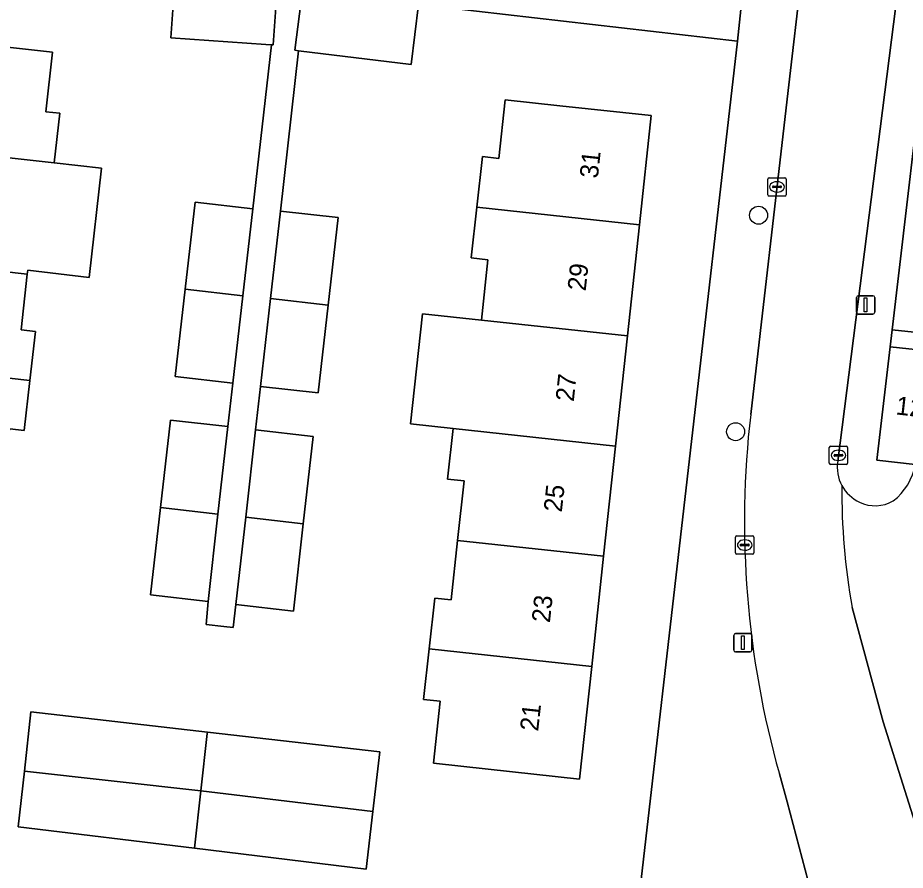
# Model space of a CAD drawing. Extents: x 162026 to 163502, y 387295 to 388169.
# Drawn here: x 162444.62 to 162492.97, y 387700.63 to 387747.09 of the extents above; entities that cross this region are included whole.
import ezdxf

# ---------------------------------------------------------------- set-up
doc = ezdxf.new("R2010")
doc.units = 0
for name, color, linetype in [('IMGEO_Boom', 7, 'Continuous'), ('IMGEO_Erf', 7, 'Continuous'), ('IMGEO_Groenvoorziening', 7, 'Continuous'), ('IMGEO_Kolk', 7, 'Continuous'), ('IMGEO_Lichtmast', 7, 'Continuous'), ('IMGEO_Pand', 7, 'Continuous'), ('IMGEO_Pand_nummerreeks', 7, 'Continuous'), ('IMGEO_Parkeervlak_open', 7, 'Continuous'), ('IMGEO_Rijbaan_lokaal_open', 7, 'Continuous'), ('IMGEO_Voetpad_open', 7, 'Continuous')]:
    doc.layers.add(name, color=color, linetype=linetype)

msp = doc.modelspace()

# ---------------------------------------------------------------- linework, layer by layer
at = {"layer": 'IMGEO_Boom'}
for centre in [(162484.977, 387736.328), (162483.728, 387724.532)]:
    msp.add_circle(centre, 0.489, dxfattribs=at)
at = {"layer": 'IMGEO_Erf'}
for points in [[(162495.6, 387752.476), (162494.973, 387750), (162494.279, 387747.259), (162492.259, 387730.082), (162494.645, 387729.836), (162520.514, 387727.17), (162539.426, 387725.085), (162541.672, 387745.5)], [(162478.34, 387698.075), (162483.821, 387745.82), (162466.456, 387747.814), (162466.055, 387744.538), (162459.921, 387745.291), (162458.93, 387736.554), (162462.069, 387736.197), (162461.528, 387731.428), (162460.986, 387726.646), (162457.846, 387727.002), (162457.577, 387724.631), (162460.716, 387724.275), (162460.176, 387719.515), (162459.636, 387714.756), (162456.497, 387715.112), (162456.355, 387713.866), (162455.849, 387713.923), (162454.88, 387714.033), (162454.985, 387715.28), (162451.845, 387715.638), (162452.388, 387720.397), (162452.932, 387725.167), (162456.072, 387724.809), (162456.342, 387727.183), (162453.203, 387727.541), (162453.744, 387732.292), (162454.286, 387737.042), (162457.426, 387736.684), (162458.444, 387745.612), (162458.142, 387745.633), (162452.965, 387745.998), (162453.181, 387749.067)], [(162443.545, 387745.548), (162446.519, 387745.215), (162446.155, 387741.965), (162446.903, 387741.882), (162446.6, 387739.174), (162449.179, 387738.885), (162448.504, 387732.942), (162445.16, 387733.326), (162445.136, 387733.112), (162444.796, 387730.079), (162445.578, 387729.992), (162445.28, 387727.328), (162444.975, 387724.601), (162444.184, 387724.69)]]:
    msp.add_lwpolyline(points, dxfattribs=at)
for points in [[(162469.946, 387739.524), (162470.827, 387739.424), (162471.171, 387742.616), (162474.154, 387742.294), (162479.125, 387741.758), (162478.483, 387735.806), (162477.83, 387729.752), (162477.182, 387723.75), (162476.535, 387717.75), (162475.887, 387711.744), (162475.225, 387705.604), (162470.254, 387706.14), (162467.271, 387706.462), (162467.635, 387709.842), (162466.728, 387709.944), (162467.038, 387712.699), (162467.35, 387715.462), (162468.231, 387715.362), (162468.581, 387718.608), (162468.93, 387721.848), (162468.023, 387721.95), (162468.333, 387724.705), (162466.013, 387724.955), (162466.661, 387730.957), (162469.876, 387730.61), (162470.231, 387733.904), (162469.324, 387734.006), (162469.634, 387736.761)], [(162454.956, 387708.166), (162464.345, 387707.086), (162463.971, 387703.839), (162463.608, 387700.688), (162454.253, 387701.83), (162444.65, 387703.003), (162444.979, 387706.034), (162445.331, 387709.274)]]:
    msp.add_lwpolyline(points, close=True, dxfattribs=at)
at = {"layer": 'IMGEO_Groenvoorziening'}
msp.add_lwpolyline([(162494.527, 387728.901), (162492.151, 387729.163), (162491.424, 387722.983), (162493.513, 387722.751), (162493.753, 387722.725)], close=True, dxfattribs=at)
at = {"layer": 'IMGEO_Kolk'}
for p, q in [((162485.481, 387737.447), (162485.481, 387738.299)), ((162485.556, 387738.373), (162486.408, 387738.373)), ((162485.969, 387738.153), (162485.994, 387738.153)), ((162486.482, 387738.299), (162486.482, 387737.447)), ((162485.74, 387737.867), (162485.74, 387737.879)), ((162486.178, 387737.83), (162485.78, 387737.83)), ((162485.783, 387737.916), (162486.181, 387737.916)), ((162486.224, 387737.879), (162486.224, 387737.867)), ((162486.408, 387737.373), (162485.556, 387737.373)), ((162485.992, 387737.593), (162485.967, 387737.593)), ((162488.83, 387722.818), (162488.83, 387723.67)), ((162488.905, 387723.744), (162489.757, 387723.744)), ((162489.831, 387723.67), (162489.831, 387722.818)), ((162489.089, 387723.238), (162489.089, 387723.25)), ((162489.527, 387723.201), (162489.129, 387723.201)), ((162489.132, 387723.287), (162489.53, 387723.287)), ((162489.318, 387723.524), (162489.343, 387723.524)), ((162489.573, 387723.25), (162489.573, 387723.238)), ((162489.757, 387722.744), (162488.905, 387722.744)), ((162489.341, 387722.964), (162489.316, 387722.964)), ((162483.8, 387718.855), (162484.652, 387718.855)), ((162483.725, 387717.929), (162483.725, 387718.781)), ((162483.984, 387718.349), (162483.984, 387718.361)), ((162484.422, 387718.312), (162484.024, 387718.312)), ((162484.027, 387718.398), (162484.425, 387718.398)), ((162484.213, 387718.635), (162484.238, 387718.635)), ((162484.468, 387718.361), (162484.468, 387718.349)), ((162484.726, 387718.781), (162484.726, 387717.929)), ((162484.652, 387717.855), (162483.8, 387717.855)), ((162484.236, 387718.075), (162484.211, 387718.075))]:
    msp.add_line(p, q, dxfattribs=at)
for points in [[(162485.481, 387737.447), (162485.481, 387738.299)], [(162485.556, 387738.373), (162486.408, 387738.373)], [(162486.482, 387738.299), (162486.482, 387737.447)], [(162486.408, 387737.373), (162485.556, 387737.373)], [(162488.83, 387722.818), (162488.83, 387723.67)], [(162488.905, 387723.744), (162489.757, 387723.744)], [(162489.831, 387723.67), (162489.831, 387722.818)], [(162489.757, 387722.744), (162488.905, 387722.744)], [(162483.8, 387718.855), (162484.652, 387718.855)], [(162483.725, 387717.929), (162483.725, 387718.781)], [(162484.726, 387718.781), (162484.726, 387717.929)], [(162484.652, 387717.855), (162483.8, 387717.855)]]:
    msp.add_lwpolyline(points, dxfattribs=at)
for centre, radius, start, end in [((162485.558, 387738.297), 0.0765, 91.552, 178.448), ((162485.558, 387738.297), 0.0765, 91.552, 178.448), ((162486.406, 387738.297), 0.0765, 1.552, 88.448), ((162486.406, 387738.297), 0.0765, 1.552, 88.448), ((162485.78, 387737.876), 0.0403, 85.8775, 175.7526), ((162485.777, 387737.866), 0.0366, 178.938, 274.7102), ((162486.181, 387737.873), 0.043, 264.8664, 352.4533), ((162486.185, 387737.878), 0.0386, 1.7309, 96.639), ((162485.558, 387737.449), 0.0765, 181.552, 268.448), ((162485.558, 387737.449), 0.0765, 181.552, 268.448), ((162486.406, 387737.449), 0.0765, 271.552, 358.448), ((162486.406, 387737.449), 0.0765, 271.552, 358.448), ((162488.907, 387723.668), 0.0765, 91.552, 178.448), ((162488.907, 387723.668), 0.0765, 91.552, 178.448), ((162489.755, 387723.668), 0.0765, 1.552, 88.448), ((162489.755, 387723.668), 0.0765, 1.552, 88.448), ((162489.129, 387723.247), 0.0403, 85.8775, 175.7526), ((162489.126, 387723.237), 0.0366, 178.938, 274.7102), ((162489.53, 387723.244), 0.043, 264.8664, 352.4533), ((162489.534, 387723.249), 0.0386, 1.7309, 96.639), ((162488.907, 387722.82), 0.0765, 181.552, 268.448), ((162488.907, 387722.82), 0.0765, 181.552, 268.448), ((162489.755, 387722.82), 0.0765, 271.552, 358.448), ((162489.755, 387722.82), 0.0765, 271.552, 358.448), ((162483.802, 387718.779), 0.0765, 91.552, 178.448), ((162483.802, 387718.779), 0.0765, 91.552, 178.448), ((162484.65, 387718.779), 0.0765, 1.552, 88.448), ((162484.65, 387718.779), 0.0765, 1.552, 88.448), ((162484.024, 387718.358), 0.0403, 85.8775, 175.7526), ((162484.021, 387718.348), 0.0366, 178.938, 274.7102), ((162484.425, 387718.355), 0.043, 264.8664, 352.4533), ((162484.429, 387718.36), 0.0386, 1.7309, 96.639), ((162483.802, 387717.931), 0.0765, 181.552, 268.448), ((162483.802, 387717.931), 0.0765, 181.552, 268.448), ((162484.65, 387717.931), 0.0765, 271.552, 358.448), ((162484.65, 387717.931), 0.0765, 271.552, 358.448)]:
    msp.add_arc(centre, radius, start, end, dxfattribs=at)
for centre, major_axis, ratio, start_param, end_param in [((162485.968, 387737.873), (-0.387, 0.002), 0.722429, 4.712389, 7.853982), ((162485.993, 387737.873), (-0.39, 0.002), 0.717154, 1.570796, 4.712389), ((162489.317, 387723.244), (-0.387, 0.002), 0.722429, 4.712389, 7.853982), ((162489.342, 387723.244), (-0.39, 0.002), 0.717154, 1.570796, 4.712389), ((162484.212, 387718.355), (-0.387, 0.002), 0.722429, 4.712389, 7.853982), ((162484.237, 387718.355), (-0.39, 0.002), 0.717154, 1.570796, 4.712389)]:
    msp.add_ellipse(centre, major_axis=major_axis, ratio=ratio, start_param=start_param, end_param=end_param, dxfattribs=at)
at = {"layer": 'IMGEO_Lichtmast'}
for p, q in [((162490.413, 387731.943), (162491.203, 387731.943)), ((162491.203, 387731.943), (162490.413, 387731.943)), ((162490.313, 387731.043), (162490.313, 387731.843)), ((162490.313, 387731.843), (162490.313, 387731.043)), ((162491.303, 387731.843), (162491.303, 387731.043)), ((162491.303, 387731.043), (162491.303, 387731.843)), ((162491.203, 387730.943), (162490.413, 387730.943)), ((162490.413, 387730.943), (162491.203, 387730.943)), ((162483.722, 387713.53), (162484.512, 387713.53)), ((162484.512, 387713.53), (162483.722, 387713.53)), ((162483.622, 387712.63), (162483.622, 387713.43)), ((162483.622, 387713.43), (162483.622, 387712.63)), ((162484.612, 387713.43), (162484.612, 387712.63)), ((162484.612, 387712.63), (162484.612, 387713.43)), ((162484.512, 387712.53), (162483.722, 387712.53)), ((162483.722, 387712.53), (162484.512, 387712.53))]:
    msp.add_line(p, q, dxfattribs=at)
for points in [[(162490.733, 387731.818), (162490.883, 387731.818), (162490.883, 387731.068), (162490.733, 387731.068), (162490.733, 387731.818)], [(162484.042, 387713.405), (162484.192, 387713.405), (162484.192, 387712.655), (162484.042, 387712.655), (162484.042, 387713.405)]]:
    msp.add_lwpolyline(points, dxfattribs=at)
for centre, start, end in [((162490.413, 387731.843), 90, 180), ((162490.413, 387731.843), 90, 180), ((162491.203, 387731.843), 0, 90), ((162491.203, 387731.843), 360, 90), ((162490.413, 387731.043), 180, 270), ((162490.413, 387731.043), 180, 270), ((162491.203, 387731.043), 270, 0), ((162491.203, 387731.043), 270, 0), ((162483.722, 387713.43), 90, 180), ((162483.722, 387713.43), 90, 180), ((162484.512, 387713.43), 0, 90), ((162484.512, 387713.43), 360, 90), ((162483.722, 387712.63), 180, 270), ((162483.722, 387712.63), 180, 270), ((162484.512, 387712.63), 270, 0), ((162484.512, 387712.63), 270, 0)]:
    msp.add_arc(centre, 0.1, start, end, dxfattribs=at)
at = {"layer": 'IMGEO_Pand'}
for points in [[(162458.757, 387748.674), (162453.181, 387749.067), (162452.965, 387745.998), (162458.142, 387745.633), (162458.444, 387745.612), (162458.541, 387745.605)], [(162466.456, 387747.814), (162460.124, 387748.59), (162459.722, 387745.315), (162459.921, 387745.291), (162466.055, 387744.538)], [(162446.6, 387739.174), (162446.903, 387741.882), (162446.155, 387741.965), (162446.519, 387745.215), (162443.545, 387745.548), (162438.576, 387746.104), (162437.91, 387740.147)], [(162469.946, 387739.524), (162469.634, 387736.761), (162478.483, 387735.806), (162479.125, 387741.758), (162474.154, 387742.294), (162471.171, 387742.616), (162470.827, 387739.424)], [(162446.6, 387739.174), (162437.91, 387740.147), (162437.222, 387733.998), (162445.136, 387733.112), (162445.16, 387733.326), (162448.504, 387732.942), (162449.179, 387738.885)], [(162457.426, 387736.684), (162454.286, 387737.042), (162453.744, 387732.292), (162456.884, 387731.935)], [(162469.324, 387734.006), (162470.231, 387733.904), (162469.876, 387730.61), (162477.83, 387729.752), (162478.483, 387735.806), (162469.634, 387736.761)], [(162458.93, 387736.554), (162458.388, 387731.784), (162461.528, 387731.428), (162462.069, 387736.197)], [(162437.222, 387733.998), (162436.584, 387728.302), (162445.28, 387727.328), (162445.578, 387729.992), (162444.796, 387730.079), (162445.136, 387733.112)], [(162456.884, 387731.935), (162453.744, 387732.292), (162453.203, 387727.541), (162456.342, 387727.183)], [(162461.528, 387731.428), (162458.388, 387731.784), (162457.846, 387727.002), (162460.986, 387726.646)], [(162468.333, 387724.705), (162477.182, 387723.75), (162477.83, 387729.752), (162469.876, 387730.61), (162466.661, 387730.957), (162466.013, 387724.955)], [(162443.805, 387721.304), (162444.184, 387724.69), (162444.975, 387724.601), (162445.28, 387727.328), (162436.584, 387728.302), (162435.9, 387722.189)], [(162456.072, 387724.809), (162452.932, 387725.167), (162452.388, 387720.397), (162455.528, 387720.039)], [(162457.577, 387724.631), (162457.037, 387719.871), (162460.176, 387719.515), (162460.716, 387724.275)], [(162468.93, 387721.848), (162468.581, 387718.608), (162476.535, 387717.75), (162477.182, 387723.75), (162468.333, 387724.705), (162468.023, 387721.95)], [(162455.528, 387720.039), (162452.388, 387720.397), (162451.845, 387715.638), (162454.985, 387715.28)], [(162460.176, 387719.515), (162457.037, 387719.871), (162456.497, 387715.112), (162459.636, 387714.756)], [(162467.35, 387715.462), (162467.038, 387712.699), (162475.887, 387711.744), (162476.535, 387717.75), (162468.581, 387718.608), (162468.231, 387715.362)], [(162466.728, 387709.944), (162467.635, 387709.842), (162467.271, 387706.462), (162470.254, 387706.14), (162475.225, 387705.604), (162475.887, 387711.744), (162467.038, 387712.699)], [(162454.946, 387708.078), (162454.956, 387708.166), (162445.331, 387709.274), (162444.979, 387706.034), (162454.6, 387704.959)], [(162463.971, 387703.839), (162464.345, 387707.086), (162454.956, 387708.166), (162454.946, 387708.078), (162454.6, 387704.959)], [(162444.979, 387706.034), (162444.65, 387703.003), (162454.253, 387701.83), (162454.6, 387704.959)], [(162454.6, 387704.959), (162454.253, 387701.83), (162463.608, 387700.688), (162463.971, 387703.839)]]:
    msp.add_lwpolyline(points, close=True, dxfattribs=at)
at = {"layer": 'IMGEO_Parkeervlak_open'}
msp.add_lwpolyline([(162490.077, 387714.957), (162491.77, 387708.72), (162496.496, 387693.763), (162498.844, 387685.91)], dxfattribs=at)
for centre, radius, start, end in [((162490.417, 387723.266), 3.138, 307.0468, 350.5611), ((162525.061, 387721.262), 35.547, 179.4535, 190.2165), ((162491.376, 387722.605), 2.114, 208.3598, 244.9377), ((162491.327, 387722.45), 1.953, 244.2957, 300.1528)]:
    msp.add_arc(centre, radius, start, end, dxfattribs=at)
at = {"layer": 'IMGEO_Rijbaan_lokaal_open'}
for points in [[(162490.431, 387778.03), (162487.406, 387750.172), (162487.386, 387750), (162486.537, 387742.661), (162484.548, 387725.474)], [(162489.288, 387722.919), (162492.448, 387747.747)], [(162498.844, 387685.91), (162496.496, 387693.763), (162491.77, 387708.72), (162490.077, 387714.957)], [(162486.11, 387705.881), (162486.539, 387704.356), (162488.177, 387698.19), (162490.602, 387687.877)]]:
    msp.add_lwpolyline(points, dxfattribs=at)
for centre, radius, start, end in [((162534.991, 387719.637), 50.78, 173.3991, 195.7171), ((162491.366, 387722.598), 2.103, 171.2288, 208.3156), ((162525.061, 387721.262), 35.547, 179.4535, 190.2165)]:
    msp.add_arc(centre, radius, start, end, dxfattribs=at)
at = {"layer": 'IMGEO_Voetpad_open'}
for points in [[(162484.548, 387725.474), (162486.537, 387742.661), (162487.386, 387750), (162487.406, 387750.172), (162490.431, 387778.03)], [(162487.392, 387776.92), (162486.062, 387765.339), (162484.018, 387747.533), (162483.821, 387745.82), (162478.34, 387698.075), (162471.82, 387639.553), (162471.648, 387638.013), (162471.035, 387632.515)], [(162494.345, 387755.452), (162492.907, 387750), (162492.448, 387747.747), (162489.288, 387722.919)], [(162458.757, 387748.674), (162458.541, 387745.605), (162458.444, 387745.612), (162457.426, 387736.684), (162456.884, 387731.935), (162456.342, 387727.183), (162456.072, 387724.809), (162455.528, 387720.039), (162454.985, 387715.28), (162454.88, 387714.033), (162455.849, 387713.923), (162456.355, 387713.866), (162456.497, 387715.112), (162457.037, 387719.871), (162457.577, 387724.631), (162457.846, 387727.002), (162458.388, 387731.784), (162458.93, 387736.554), (162459.921, 387745.291), (162459.722, 387745.315), (162460.124, 387748.59)], [(162466.456, 387747.814), (162483.821, 387745.82), (162484.018, 387747.533)], [(162493.513, 387722.751), (162491.424, 387722.983), (162492.151, 387729.163), (162492.259, 387730.082), (162494.279, 387747.259)], [(162490.602, 387687.877), (162488.177, 387698.19), (162486.539, 387704.356), (162486.11, 387705.881)]]:
    msp.add_lwpolyline(points, dxfattribs=at)
msp.add_lwpolyline([(162550.204, 387723.897), (162539.426, 387725.085), (162520.514, 387727.17), (162494.645, 387729.836), (162492.259, 387730.082), (162492.151, 387729.163), (162494.527, 387728.901), (162519.107, 387726.189), (162518.403, 387719.984), (162519.319, 387719.882), (162519.985, 387726.106), (162552.467, 387722.453), (162553.062, 387722.386), (162553.167, 387723.389), (162553.186, 387723.568)], close=True, dxfattribs=at)
for centre, radius, start, end in [((162534.991, 387719.637), 50.78, 173.3991, 195.7171), ((162491.366, 387722.598), 2.103, 171.2288, 208.3156), ((162490.417, 387723.266), 3.138, 307.0468, 350.5611), ((162491.376, 387722.605), 2.114, 208.3598, 244.9377), ((162491.327, 387722.45), 1.953, 244.2957, 300.1528)]:
    msp.add_arc(centre, radius, start, end, dxfattribs=at)

# ---------------------------------------------------------------- texts
at = {"layer": 'IMGEO_Pand_nummerreeks'}
for s, rotation, p in [('31', 83.8432, (162476.219, 387738.306)), ('29', 83.8432, (162475.557, 387732.169)), ('27', 83.8432, (162474.907, 387726.143)), ('120/G10', 353.5505, (162492.423, 387725.478)), ('25', 83.8432, (162474.257, 387720.117)), ('23', 83.8432, (162473.607, 387714.092)), ('21', 83.8432, (162472.969, 387708.178))]:
    msp.add_text(s, height=1, rotation=rotation, dxfattribs=at).set_placement(p)

doc.saveas('drawing.dxf')
